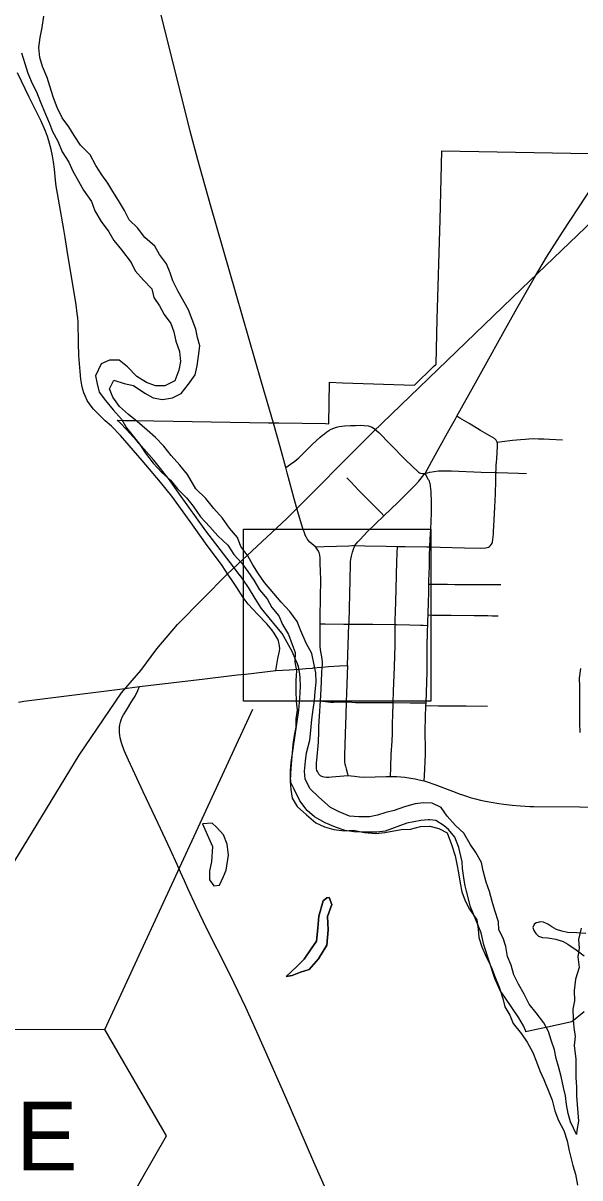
# Model space of a CAD drawing. Extents: x 0 to 680, y 0 to 440.
# Drawn here: x 391.77 to 414.44, y 243.12 to 290.12 of the extents above; entities that cross this region are included whole.
import ezdxf

# ---------------------------------------------------------------- set-up
doc = ezdxf.new("R2010")
doc.units = 0
for name, color, linetype in [('DV_X_Corp_Line', 7, 'Continuous'), ('GM_X_City_Street', 7, 'Continuous'), ('GM_X_County_Road', 7, 'Continuous'), ('GM_X_Major_River', 7, 'Continuous'), ('GM_X_Minor_Lake', 7, 'Continuous'), ('GM_X_State_Route', 7, 'Continuous'), ('GM_X_Township_Road', 7, 'Continuous'), ('RD_X_RR_2', 7, 'Continuous'), ('SC_Shading3', 7, 'Continuous'), ('SH_Border', 7, 'Continuous')]:
    doc.layers.add(name, color=color, linetype=linetype)

msp = doc.modelspace()

# ---------------------------------------------------------------- linework, layer by layer
at = {"layer": 'DV_X_Corp_Line'}
for points in [[(414.613, 249.879), (414.112, 249.473), (412.995, 249.229), (412.601, 249.143), (412.239, 249.063), (412.233, 249.089), (412.142, 249.315), (411.951, 249.632), (411.381, 250.477), (411.197, 250.751), (410.972, 251.237), (410.739, 251.941), (410.521, 252.603), (410.415, 253.089), (409.985, 254.153), (409.816, 254.794), (409.772, 255.007), (409.724, 255.237), (409.661, 255.709), (409.639, 255.984), (409.505, 256.568), (409.343, 256.984), (409.083, 257.301), (408.907, 257.449), (408.568, 257.66), (408.322, 257.695), (408.263, 257.689), (407.963, 257.66), (407.392, 257.554), (406.505, 257.23), (406.167, 257.187), (405.646, 257.187), (405.237, 257.208), (404.885, 257.264), (404.483, 257.391), (404.061, 257.567), (403.638, 257.813), (403.335, 258.067), (403.032, 258.468), (402.786, 258.961), (402.673, 259.208), (402.652, 259.454), (402.652, 259.694), (402.687, 260.025), (402.996, 262.152), (403.031, 262.638), (403.052, 262.856), (403.066, 263.145), (403.052, 263.441), (403.03, 263.645), (403.026, 263.68), (403.024, 263.701), (402.994, 263.843), (402.974, 263.934), (402.947, 264.005), (402.935, 264.039), (402.876, 264.194), (402.721, 264.546), (402.516, 264.913), (402.319, 265.279), (402.094, 265.532), (401.467, 266.286), (401.213, 266.694), (400.949, 267.143), (400.739, 267.444), (400.617, 267.62), (400.611, 267.627), (400.206, 268.153), (400.199, 268.162), (399.203, 269.448), (398.139, 270.942), (397.726, 271.534), (397.087, 272.329), (396.681, 272.796), (396.388, 273.134), (395.978, 273.573), (395.721, 273.847), (395.596, 273.954), (395.895, 273.949), (396.245, 273.943), (396.314, 273.942), (401.756, 273.854), (401.965, 273.851), (402.174, 273.847), (404.074, 273.817), (404.214, 273.814), (404.241, 275.497), (404.775, 275.478), (407.703, 275.378), (408.478, 276.138), (408.58, 276.238), (408.631, 278.061), (408.743, 282.103), (408.821, 284.918), (415.576, 284.794)], [(414.674, 253.068), (414.314, 253.088), (413.932, 253.109), (413.697, 253.157), (413.489, 253.227), (413.295, 253.337), (413.128, 253.441), (412.955, 253.524), (412.823, 253.545), (412.733, 253.517), (412.65, 253.497), (412.574, 253.434), (412.525, 253.316), (412.567, 253.185), (412.643, 253.067), (412.754, 252.963), (412.914, 252.901), (413.128, 252.894), (413.454, 252.838), (413.752, 252.742), (413.939, 252.631), (414.279, 252.402), (414.605, 252.153)]]:
    msp.add_lwpolyline(points, dxfattribs=at)
at = {"layer": 'GM_X_City_Street'}
for points in [[(410.796, 268.856), (410.839, 268.912), (410.861, 268.951), (410.875, 268.994), (410.895, 269.107), (410.908, 269.209), (410.918, 269.319), (410.924, 269.444), (410.939, 269.646), (410.977, 270.411), (410.996, 270.958), (411.014, 271.505), (411.015, 271.828), (411.022, 271.951), (411.031, 272.12), (411.042, 272.252), (411.053, 272.378), (411.084, 272.892), (411.086, 272.949), (411.082, 272.979), (411.078, 273.014), (411.065, 273.059), (411.054, 273.091), (411.04, 273.116), (411.025, 273.142), (410.999, 273.171), (410.954, 273.205), (410.765, 273.315), (410.392, 273.541), (409.925, 273.819), (409.549, 274.043), (409.428, 274.115)], [(402.47, 272.024), (402.659, 272.16), (402.832, 272.288), (402.997, 272.427), (403.54, 272.965), (403.862, 273.265), (403.952, 273.34), (404.033, 273.405), (404.131, 273.476), (404.214, 273.533), (404.311, 273.59), (404.414, 273.637), (404.521, 273.671), (404.63, 273.697), (404.74, 273.715), (404.852, 273.724), (405.099, 273.735), (405.304, 273.743), (405.507, 273.748), (405.658, 273.74), (405.81, 273.72), (405.981, 273.671)], [(405.981, 273.671), (406.075, 273.604), (406.244, 273.457), (406.717, 272.983), (407.34, 272.346), (407.86, 271.841), (407.909, 271.812), (407.952, 271.801), (408.029, 271.789), (408.132, 271.791), (408.325, 271.841), (408.501, 271.872), (408.681, 271.89), (408.886, 271.899), (409.212, 271.892), (410.414, 271.844), (411.015, 271.828), (411.07, 271.827), (411.941, 271.797), (412.26, 271.782)], [(411.065, 273.059), (411.269, 273.086), (411.699, 273.141), (412.023, 273.169), (412.202, 273.182), (412.357, 273.192), (412.565, 273.205), (412.75, 273.201), (412.967, 273.198), (413.197, 273.185), (413.733, 273.161)], [(408.33, 268.805), (408.343, 269.111), (408.361, 269.52), (408.389, 270.177), (408.396, 270.505), (408.393, 270.732), (408.388, 270.926), (408.381, 271.049), (408.373, 271.159), (408.36, 271.268), (408.354, 271.314), (408.341, 271.369), (408.33, 271.411), (408.312, 271.468), (408.298, 271.499), (408.277, 271.535), (408.132, 271.791)], [(404.942, 271.613), (405.092, 271.459), (405.274, 271.273), (405.429, 271.114), (405.632, 270.906), (405.829, 270.705), (406.037, 270.492), (406.194, 270.331), (406.341, 270.182), (406.453, 270.066)], [(405.277, 268.85), (405.676, 268.838), (406.551, 268.823), (407.007, 268.818), (407.32, 268.814), (408.196, 268.806), (408.33, 268.805), (408.744, 268.793), (409.732, 268.763), (410.39, 268.751), (410.608, 268.763), (410.662, 268.773), (410.711, 268.788), (410.758, 268.818), (410.796, 268.856)], [(406.732, 259.459), (406.732, 259.581), (406.733, 259.689), (406.737, 259.871), (406.741, 260.017), (406.75, 260.186), (406.759, 260.345), (406.79, 260.89), (406.802, 261.211), (406.803, 261.433), (406.805, 261.643), (406.814, 261.937), (406.832, 262.461), (406.85, 262.933), (406.883, 263.92), (406.909, 264.797), (406.917, 265.235), (406.92, 265.64), (406.921, 265.784), (406.943, 266.551), (406.973, 267.651), (406.989, 268.2), (406.999, 268.529), (407.007, 268.818)], [(403.831, 259.521), (403.806, 259.553), (403.775, 259.599), (403.748, 259.654), (403.729, 259.705), (403.717, 259.78), (403.708, 259.851), (403.712, 259.912), (403.717, 260.008), (403.729, 260.116), (403.79, 260.85), (403.794, 260.955), (403.803, 261.164), (403.809, 261.487), (403.833, 261.914), (403.874, 262.541), (403.904, 263.008), (403.918, 263.343), (403.931, 263.656), (403.941, 263.904), (403.953, 263.992), (403.956, 264.047), (403.954, 264.102), (403.937, 264.225), (403.91, 264.408), (403.886, 264.531), (403.873, 264.628), (403.864, 264.746), (403.861, 265.182), (403.867, 265.51), (403.864, 265.674), (403.859, 265.947), (403.874, 266.712), (403.885, 267.477), (403.881, 267.803), (403.867, 268.133), (403.857, 268.352), (403.843, 268.46), (403.817, 268.565), (403.772, 268.663), (403.681, 268.789)], [(408.096, 259.273), (408.107, 259.489), (408.149, 260.358), (408.144, 260.739), (408.139, 261.101), (408.142, 261.306), (408.152, 261.869), (408.17, 262.335), (408.171, 262.455), (408.212, 263.711), (408.224, 264.698), (408.238, 265.408), (408.24, 265.607), (408.248, 265.806), (408.257, 266.03), (408.26, 266.113), (408.269, 266.511), (408.28, 266.973), (408.285, 267.282), (408.287, 267.406), (408.304, 267.734), (408.308, 267.973), (408.315, 268.443), (408.316, 268.538), (408.323, 268.707), (408.33, 268.805)], [(408.285, 267.282), (408.56, 267.28), (408.795, 267.278), (409.043, 267.277), (409.343, 267.275), (409.63, 267.273), (409.933, 267.271), (410.23, 267.269), (410.527, 267.267), (410.777, 267.266), (411.216, 267.263)], [(408.257, 266.03), (408.436, 266.027), (409.189, 266.016), (410.13, 266.007), (410.368, 266.005), (410.693, 266.002), (410.869, 266), (411.113, 265.997)], [(403.864, 265.674), (404.07, 265.671), (404.821, 265.66), (405.035, 265.656)], [(405.035, 265.656), (406.001, 265.656), (406.92, 265.64), (406.97, 265.639), (407.508, 265.632), (407.941, 265.619), (408.05, 265.615), (408.24, 265.607)], [(403.874, 262.541), (403.962, 262.526), (404.073, 262.507), (404.173, 262.493), (404.3, 262.486), (404.419, 262.485), (404.521, 262.488), (404.632, 262.492), (404.742, 262.493), (404.922, 262.494)], [(404.922, 262.494), (405.147, 262.481), (405.303, 262.474), (405.606, 262.466), (406.469, 262.462), (406.832, 262.461), (407.524, 262.46), (407.951, 262.456), (408.171, 262.455)], [(408.17, 262.335), (408.37, 262.341), (408.683, 262.337), (409.035, 262.335), (409.805, 262.326), (410.681, 262.322)], [(403.831, 259.521), (403.861, 259.496), (403.886, 259.479), (403.919, 259.463), (403.955, 259.452), (404.02, 259.441), (404.123, 259.433), (404.221, 259.43), (404.332, 259.436), (404.99, 259.498)]]:
    msp.add_lwpolyline(points, dxfattribs=at)
at = {"layer": 'GM_X_County_Road'}
for p, q in [((404.972, 263.972), (405.035, 265.656)), ((400.828, 263.627), (402.06, 263.764))]:
    msp.add_line(p, q, dxfattribs=at)
for points in [[(401.963, 273.829), (401.467, 275.508), (400.44, 279.081), (399.382, 282.759), (398.878, 284.549), (398.572, 285.713), (398.118, 287.516), (397.49, 290.064), (396.993, 292.082), (396.653, 293.462), (396.556, 293.857)], [(402.47, 272.024), (402.231, 272.866), (401.963, 273.829)], [(403.681, 268.789), (403.517, 268.928), (403.442, 268.998), (403.377, 269.067), (403.338, 269.124), (403.299, 269.188), (403.258, 269.276), (403.221, 269.376), (403.148, 269.594), (402.956, 270.229), (402.802, 270.76), (402.521, 271.817), (402.47, 272.024)], [(405.277, 268.85), (405.181, 268.844), (405.024, 268.834), (404.02, 268.807), (403.681, 268.789)], [(405.035, 265.656), (405.037, 265.721), (405.078, 267.458), (405.098, 268.107), (405.103, 268.187), (405.115, 268.3), (405.134, 268.422), (405.161, 268.529), (405.178, 268.588), (405.204, 268.663), (405.277, 268.85)], [(402.06, 263.764), (402.606, 263.795), (403.001, 263.824)], [(403.001, 263.824), (403.28, 263.848), (403.552, 263.871), (403.591, 263.874)], [(403.591, 263.874), (403.746, 263.888), (403.941, 263.904)], [(403.941, 263.904), (404.203, 263.926), (404.645, 263.953), (404.972, 263.972)], [(404.972, 263.972), (404.932, 262.844), (404.922, 262.494)], [(396.511, 263.112), (397.545, 263.24), (399.064, 263.419), (400.476, 263.588), (400.828, 263.627)], [(404.367, 242.057), (403.61, 243.756), (403.306, 244.457), (402.473, 246.361), (401.281, 249.063), (400.83, 250.06), (400.366, 251.051), (399.928, 251.933), (399.429, 252.906), (399.107, 253.547), (398.813, 254.164), (398.478, 254.9), (398.334, 255.217), (398.178, 255.563), (398.034, 255.87), (397.749, 256.495), (397.272, 257.539), (396.662, 258.832), (396.062, 260.121), (395.887, 260.52), (395.775, 260.825), (395.719, 261.033), (395.701, 261.139), (395.689, 261.244), (395.687, 261.351), (395.693, 261.457), (395.709, 261.562), (395.733, 261.665), (395.766, 261.767), (395.807, 261.866), (395.854, 261.962), (395.972, 262.158), (396.199, 262.516), (396.328, 262.727), (396.439, 262.96), (396.511, 263.112)], [(404.922, 262.494), (404.907, 261.96), (404.886, 261.187), (404.855, 260.305), (404.858, 260.093), (404.858, 260.028), (404.866, 259.969), (404.887, 259.872), (404.916, 259.768), (404.957, 259.618), (404.99, 259.498)], [(404.99, 259.498), (405.255, 259.465), (405.459, 259.444), (405.671, 259.433), (406.107, 259.441), (406.545, 259.457), (406.732, 259.459)], [(406.732, 259.459), (406.765, 259.459), (406.985, 259.452), (407.142, 259.442), (407.312, 259.424), (407.472, 259.404), (407.631, 259.379), (407.732, 259.362), (407.837, 259.339), (408.011, 259.298), (408.096, 259.273)], [(408.096, 259.273), (408.217, 259.239), (408.527, 259.13), (409.247, 258.861), (409.424, 258.794), (409.528, 258.754), (409.659, 258.707), (409.818, 258.651), (409.973, 258.607), (410.186, 258.55), (410.393, 258.498), (410.591, 258.45), (410.82, 258.406), (411.143, 258.352), (411.345, 258.324), (411.686, 258.288), (412.012, 258.262), (412.206, 258.249), (412.396, 258.24), (412.557, 258.236), (414.421, 258.224), (415.846, 258.207)]]:
    msp.add_lwpolyline(points, dxfattribs=at)
at = {"layer": 'GM_X_Major_River'}
for points in [[(398.495, 275.422), (398.767, 275.804), (398.853, 276.163), (398.913, 276.562), (398.96, 276.975), (398.872, 277.323), (398.798, 277.658), (398.645, 278.048), (398.505, 278.451), (398.078, 279.192), (397.859, 279.623), (397.758, 279.958), (397.604, 280.321), (397.318, 280.7), (397.137, 281.036), (396.717, 281.39), (396.431, 281.782), (396.09, 282.108), (395.897, 282.485), (395.651, 282.89), (395.417, 283.268), (395.223, 283.605), (394.976, 283.942), (394.73, 284.32), (394.497, 284.751), (394.104, 285.145), (393.845, 285.537), (393.624, 285.887), (393.364, 286.265), (393.158, 286.683), (393.005, 287.072), (392.854, 287.555), (392.753, 287.904), (392.561, 288.348), (392.447, 288.71), (392.414, 289.124), (392.46, 289.524), (392.547, 289.936), (392.608, 290.402)], [(391.705, 288.909), (391.844, 288.467), (391.957, 288.078), (392.137, 287.661), (392.317, 287.324), (392.47, 286.895), (392.675, 286.411), (392.842, 286.034), (392.969, 285.698), (393.176, 285.308), (393.355, 284.878), (393.627, 284.459), (393.794, 284.096), (394.027, 283.679), (394.221, 283.315), (394.546, 282.856), (394.686, 282.48), (394.945, 282.048), (395.257, 281.616), (395.464, 281.265), (395.777, 280.886), (396.168, 280.372), (396.335, 280.036), (396.675, 279.656), (397.002, 279.304), (397.089, 278.942), (397.323, 278.604), (397.504, 278.254), (397.777, 277.889), (397.904, 277.554), (397.991, 277.165), (398.131, 276.749), (398.177, 276.348), (398.105, 275.989), (397.938, 275.551), (397.535, 275.358), (397.163, 275.351), (396.792, 275.491), (396.397, 275.738), (396.018, 276.132), (395.676, 276.404), (395.29, 276.398), (394.942, 276.244), (394.721, 275.767), (394.782, 275.432), (394.87, 275.097), (395.117, 274.759), (395.43, 274.38), (395.77, 274.001), (395.977, 273.65), (396.251, 273.312), (396.524, 272.96), (396.745, 272.61), (397.057, 272.204), (397.41, 271.824), (397.764, 271.511), (398.051, 271.159), (398.418, 270.793), (398.692, 270.454), (398.991, 270.022), (399.37, 269.616), (399.697, 269.25), (400.103, 268.869), (400.349, 268.491), (400.663, 268.152), (400.923, 267.801), (401.157, 267.45), (401.39, 267.059), (401.703, 266.68), (401.897, 266.329), (402.184, 265.991), (402.325, 265.642), (402.571, 265.237), (402.724, 264.834), (402.838, 264.499), (402.832, 264.125), (402.892, 263.75), (402.873, 263.364), (402.865, 262.924), (402.885, 262.523), (402.919, 262.149), (402.873, 261.803), (402.868, 261.469), (402.809, 261.123), (402.75, 260.764), (402.717, 260.417), (402.683, 259.964), (402.65, 259.591), (402.645, 259.258), (402.666, 258.924), (402.727, 258.576), (402.921, 258.239)], [(414.303, 244.886), (414.059, 245.398), (413.958, 245.746), (413.898, 246.108), (413.85, 246.455), (413.763, 246.804), (413.677, 247.246), (413.564, 247.648), (413.476, 247.983), (413.402, 248.331), (413.262, 248.721), (413.162, 249.083), (412.968, 249.433), (412.655, 249.839), (412.368, 250.19), (412.162, 250.594), (411.943, 251.012), (411.75, 251.389), (411.636, 251.778), (411.496, 252.127), (411.423, 252.542), (411.309, 252.877), (411.141, 253.214), (411.12, 253.548), (410.968, 254.004), (410.867, 254.366), (410.755, 254.782), (410.614, 255.158), (410.502, 255.613), (410.428, 255.962), (410.195, 256.366), (409.975, 256.703), (409.716, 257.148), (409.375, 257.461), (409.035, 257.84), (408.788, 258.191), (408.419, 258.371), (408.073, 258.39), (407.726, 258.343), (407.298, 258.217), (406.87, 258.078), (406.536, 257.99), (406.202, 257.876), (405.868, 257.815), (405.442, 257.809), (405.057, 257.842), (404.634, 258.023), (404.277, 258.189), (403.805, 258.611), (403.451, 258.95), (403.245, 259.341), (403.224, 259.675), (403.27, 260.074), (403.303, 260.421), (403.444, 260.939), (403.477, 261.325), (403.525, 261.778), (403.571, 262.178), (403.631, 262.55), (403.663, 262.91), (403.696, 263.296), (403.689, 263.67), (403.615, 264.005), (403.529, 264.46), (403.297, 264.878), (403.079, 265.388), (402.926, 265.765), (402.626, 266.17), (402.273, 266.55), (401.973, 266.902), (401.595, 267.349), (401.348, 267.7), (401.127, 268.064), (400.921, 268.441), (400.634, 268.82), (400.494, 269.183), (400.167, 269.562), (399.881, 269.967), (399.529, 270.36), (399.203, 270.766), (398.797, 271.16), (398.46, 271.739), (398.147, 272.119), (397.795, 272.525), (397.495, 272.904), (397.155, 273.256), (396.813, 273.543), (396.407, 273.896), (396.052, 274.183), (395.698, 274.509), (395.425, 274.888), (395.285, 275.237), (395.463, 275.581), (395.887, 275.453), (396.258, 275.367), (396.719, 275.052), (397.061, 274.859), (397.446, 274.799), (397.847, 274.859), (398.209, 275.04), (398.495, 275.422)], [(414.458, 263.845), (414.412, 263.459), (414.419, 263.125), (414.424, 262.605), (414.417, 262.151), (414.421, 261.631), (414.441, 261.243)], [(402.921, 258.239), (403.301, 257.899), (403.681, 257.572), (404.038, 257.406), (404.422, 257.306), (404.847, 257.245), (405.207, 257.266), (405.671, 257.178), (406.123, 257.143), (406.496, 257.177), (407.163, 257.299), (407.536, 257.319), (407.951, 257.419), (408.323, 257.439), (408.694, 257.339), (409.037, 257.16), (409.203, 256.69), (409.355, 256.233), (409.429, 255.885), (409.49, 255.537), (409.563, 255.122), (409.636, 254.761), (409.764, 254.398), (409.944, 254.062), (410.243, 253.63), (410.29, 253.242), (410.324, 252.908), (410.451, 252.518), (410.617, 252.115), (410.823, 251.711), (410.977, 251.322), (411.156, 250.878), (411.294, 250.422), (411.382, 250.087), (411.589, 249.737), (411.717, 249.401), (412.056, 248.982), (412.29, 248.644), (412.522, 248.226), (412.676, 247.85), (412.802, 247.474), (412.97, 247.124), (413.174, 246.627), (413.302, 246.278), (413.414, 245.849), (413.567, 245.46), (413.787, 245.055), (413.913, 244.626), (413.999, 244.225), (414.149, 243.621), (414.263, 243.273), (414.336, 242.831)], [(414.482, 253.29), (414.382, 252.824), (414.402, 252.477), (414.357, 252.118), (414.403, 251.69), (414.262, 251.212), (414.201, 250.746), (414.221, 250.332), (414.148, 249.986), (414.168, 249.572), (414.189, 249.238), (414.25, 248.877), (414.204, 248.504), (414.274, 247.956), (414.267, 247.542), (414.275, 247.195), (414.295, 246.821), (414.302, 246.448), (414.379, 245.432), (414.306, 245.047), (414.303, 244.886)]]:
    msp.add_lwpolyline(points, dxfattribs=at)
at = {"layer": 'GM_X_Minor_Lake'}
for points in [[(399.767, 255.038), (399.932, 255.382), (400.03, 255.647), (400.133, 256.259), (400.074, 256.7), (399.921, 257.076), (399.646, 257.388), (399.463, 257.551), (399.076, 257.531)], [(399.076, 257.531), (399.32, 256.98), (399.474, 256.604), (399.437, 255.977), (399.351, 255.618), (399.358, 255.245), (399.527, 255.002), (399.767, 255.038), (399.932, 255.382), (400.03, 255.647), (400.133, 256.259), (400.074, 256.7), (399.921, 257.076), (399.646, 257.388), (399.463, 257.551), (399.076, 257.531)], [(399.076, 257.531), (399.32, 256.98), (399.474, 256.604), (399.437, 255.977), (399.351, 255.618), (399.358, 255.245), (399.527, 255.002), (399.767, 255.038)], [(402.473, 251.321), (402.727, 251.357), (403.062, 251.498), (403.409, 251.599), (403.789, 252.033), (404.131, 252.587), (404.181, 253.213), (404.164, 253.761), (404.332, 254.252), (404.23, 254.534)], [(404.23, 254.534), (404.137, 254.522), (403.988, 254.391), (403.805, 253.767), (403.77, 253.287), (403.708, 252.755), (403.49, 252.438), (403.217, 252.029), (402.906, 251.728), (402.473, 251.321)], [(402.473, 251.321), (402.906, 251.728), (403.217, 252.029), (403.49, 252.438), (403.708, 252.755), (403.77, 253.287), (403.805, 253.767), (403.988, 254.391), (404.137, 254.522), (404.23, 254.534), (404.332, 254.252), (404.164, 253.761), (404.181, 253.213), (404.131, 252.587), (403.789, 252.033), (403.409, 251.599), (403.062, 251.498), (402.727, 251.357), (402.473, 251.321)]]:
    msp.add_lwpolyline(points, dxfattribs=at)
at = {"layer": 'GM_X_State_Route'}
for p, q in [((404.972, 263.972), (405.035, 265.656)), ((400.828, 263.627), (402.06, 263.764)), ((395.089, 249.161), (401.119, 262.199))]:
    msp.add_line(p, q, dxfattribs=at)
for points in [[(408.086, 271.733), (408.132, 271.791), (408.409, 272.294), (408.762, 272.925), (409.053, 273.444), (409.37, 274.011), (409.428, 274.115), (410.118, 275.348), (410.596, 276.208), (411.286, 277.452), (411.873, 278.503), (412.629, 279.837), (413.081, 280.588), (413.734, 281.601), (414.691, 283.068), (414.898, 283.389)], [(405.277, 268.85), (405.331, 268.925), (405.399, 269.012), (405.486, 269.104), (405.775, 269.409), (406.453, 270.066), (407.031, 270.625), (407.731, 271.316), (407.878, 271.476), (408.086, 271.733)], [(405.035, 265.656), (405.037, 265.721), (405.078, 267.458), (405.098, 268.107), (405.103, 268.187), (405.115, 268.3), (405.134, 268.422), (405.161, 268.529), (405.178, 268.588), (405.204, 268.663), (405.277, 268.85)], [(402.06, 263.764), (402.606, 263.795), (403.001, 263.824)], [(403.001, 263.824), (403.28, 263.848), (403.552, 263.871), (403.591, 263.874)], [(403.591, 263.874), (403.746, 263.888), (403.941, 263.904)], [(403.941, 263.904), (404.203, 263.926), (404.645, 263.953), (404.972, 263.972)], [(396.511, 263.112), (397.545, 263.24), (399.064, 263.419), (400.476, 263.588), (400.828, 263.627)], [(391.583, 262.477), (391.799, 262.521), (392.119, 262.569), (393.855, 262.785), (395.7, 263.011), (396.511, 263.112)]]:
    msp.add_lwpolyline(points, dxfattribs=at)
msp.add_lwpolyline([(395.089, 249.161), (390.089, 249.145), (387.602, 244.807), (390.116, 240.485), (395.116, 240.501), (397.602, 244.839)], close=True, dxfattribs=at)
at = {"layer": 'GM_X_Township_Road'}
msp.add_lwpolyline([(402.06, 263.764), (402.144, 264.259), (402.207, 264.563), (402.218, 264.66), (402.212, 264.765), (402.197, 264.86), (402.167, 264.965), (402.135, 265.048), (402.077, 265.154), (401.993, 265.283), (401.892, 265.418), (401.685, 265.668), (401.307, 266.059), (400.93, 266.472), (400.729, 266.734), (400.469, 267.146), (400.255, 267.47), (400.121, 267.666), (399.866, 268.041), (399.199, 268.945), (398.572, 269.834), (397.817, 270.862), (397.359, 271.44), (396.612, 272.31), (395.739, 273.33), (395.366, 273.71), (395.112, 273.935), (395.023, 274.013), (394.637, 274.403), (394.497, 274.574), (394.378, 274.762), (394.306, 274.918), (394.243, 275.066), (394.201, 275.207), (394.158, 275.378), (394.121, 275.619), (394.086, 275.932), (394.035, 276.588), (394.021, 277.089), (394.005, 277.957), (393.994, 278.123), (393.973, 278.296), (393.923, 278.651), (393.56, 280.867), (393.485, 281.389), (393.431, 281.713), (393.251, 282.725), (393.17, 283.177), (393.117, 283.477), (393.082, 283.729), (393.039, 284.168), (393.004, 284.468), (392.961, 284.709), (392.913, 284.966), (392.819, 285.324), (392.766, 285.501), (392.68, 285.721), (392.498, 286.125), (392.013, 287.107), (391.543, 288.092)], dxfattribs=at)
at = {"layer": 'RD_X_RR_2'}
msp.add_lwpolyline([(365.587, 215.989), (372.377, 226.622), (380.238, 238.84), (389.713, 253.215), (394.045, 260.328), (395.778, 262.864), (396.554, 263.768), (397.211, 264.649), (398.057, 265.641), (400.091, 267.7), (402.496, 269.941), (406.01, 273.466), (412.053, 279.303), (417.596, 284.611), (426.566, 293.352), (435.599, 302.168), (441.572, 308.078), (456.142, 322.286), (463.879, 329.729), (466.921, 332.716)], dxfattribs=at)
at = {"layer": 'SC_Shading3'}
for points in [[(414.613, 249.879), (414.112, 249.473), (412.995, 249.229), (412.601, 249.143), (412.239, 249.063), (412.233, 249.089), (412.142, 249.315), (411.951, 249.632), (411.381, 250.477), (411.197, 250.751), (410.972, 251.237), (410.739, 251.941), (410.521, 252.603), (410.415, 253.089), (409.985, 254.153), (409.816, 254.794), (409.772, 255.007), (409.724, 255.237), (409.661, 255.709), (409.639, 255.984), (409.505, 256.568), (409.343, 256.984), (409.083, 257.301), (408.907, 257.449), (408.568, 257.66), (408.322, 257.695), (408.263, 257.689), (407.963, 257.66), (407.392, 257.554), (406.505, 257.23), (406.167, 257.187), (405.646, 257.187), (405.237, 257.208), (404.885, 257.264), (404.483, 257.391), (404.061, 257.567), (403.638, 257.813), (403.335, 258.067), (403.032, 258.468), (402.786, 258.961), (402.673, 259.208), (402.652, 259.454), (402.652, 259.694), (402.687, 260.025), (402.996, 262.152), (403.031, 262.638), (403.052, 262.856), (403.066, 263.145), (403.052, 263.441), (403.03, 263.645), (403.026, 263.68), (403.024, 263.701), (402.994, 263.843), (402.974, 263.934), (402.947, 264.005), (402.935, 264.039), (402.876, 264.194), (402.721, 264.546), (402.516, 264.913), (402.319, 265.279), (402.094, 265.532), (401.467, 266.286), (401.213, 266.694), (400.949, 267.143), (400.739, 267.444), (400.617, 267.62), (400.611, 267.627), (400.206, 268.153), (400.199, 268.162), (399.203, 269.448), (398.139, 270.942), (397.726, 271.534), (397.087, 272.329), (396.681, 272.796), (396.388, 273.134), (395.978, 273.573), (395.721, 273.847), (395.596, 273.954), (395.895, 273.949), (396.245, 273.943), (396.314, 273.942), (401.756, 273.854), (401.965, 273.851), (402.174, 273.847), (404.074, 273.817), (404.214, 273.814), (404.241, 275.497), (404.775, 275.478), (407.703, 275.378), (408.478, 276.138), (408.58, 276.238), (408.631, 278.061), (408.743, 282.103), (408.821, 284.918), (415.576, 284.794)], [(414.674, 253.068), (414.314, 253.088), (413.932, 253.109), (413.697, 253.157), (413.489, 253.227), (413.295, 253.337), (413.128, 253.441), (412.955, 253.524), (412.823, 253.545), (412.733, 253.517), (412.65, 253.497), (412.574, 253.434), (412.525, 253.316), (412.567, 253.185), (412.643, 253.067), (412.754, 252.963), (412.914, 252.901), (413.128, 252.894), (413.454, 252.838), (413.752, 252.742), (413.939, 252.631), (414.279, 252.402), (414.605, 252.153)]]:
    msp.add_lwpolyline(points, dxfattribs=at)
at = {"layer": 'SH_Border'}
msp.add_lwpolyline([(400.736, 269.52), (408.361, 269.52), (408.361, 262.52), (400.736, 262.52)], close=True, dxfattribs=at)

# ---------------------------------------------------------------- texts
at = {"layer": 'GM_X_State_Route'}
msp.add_text('E', height=2.8, dxfattribs=at).set_placement((391.485, 243.423))

doc.saveas('drawing.dxf')
